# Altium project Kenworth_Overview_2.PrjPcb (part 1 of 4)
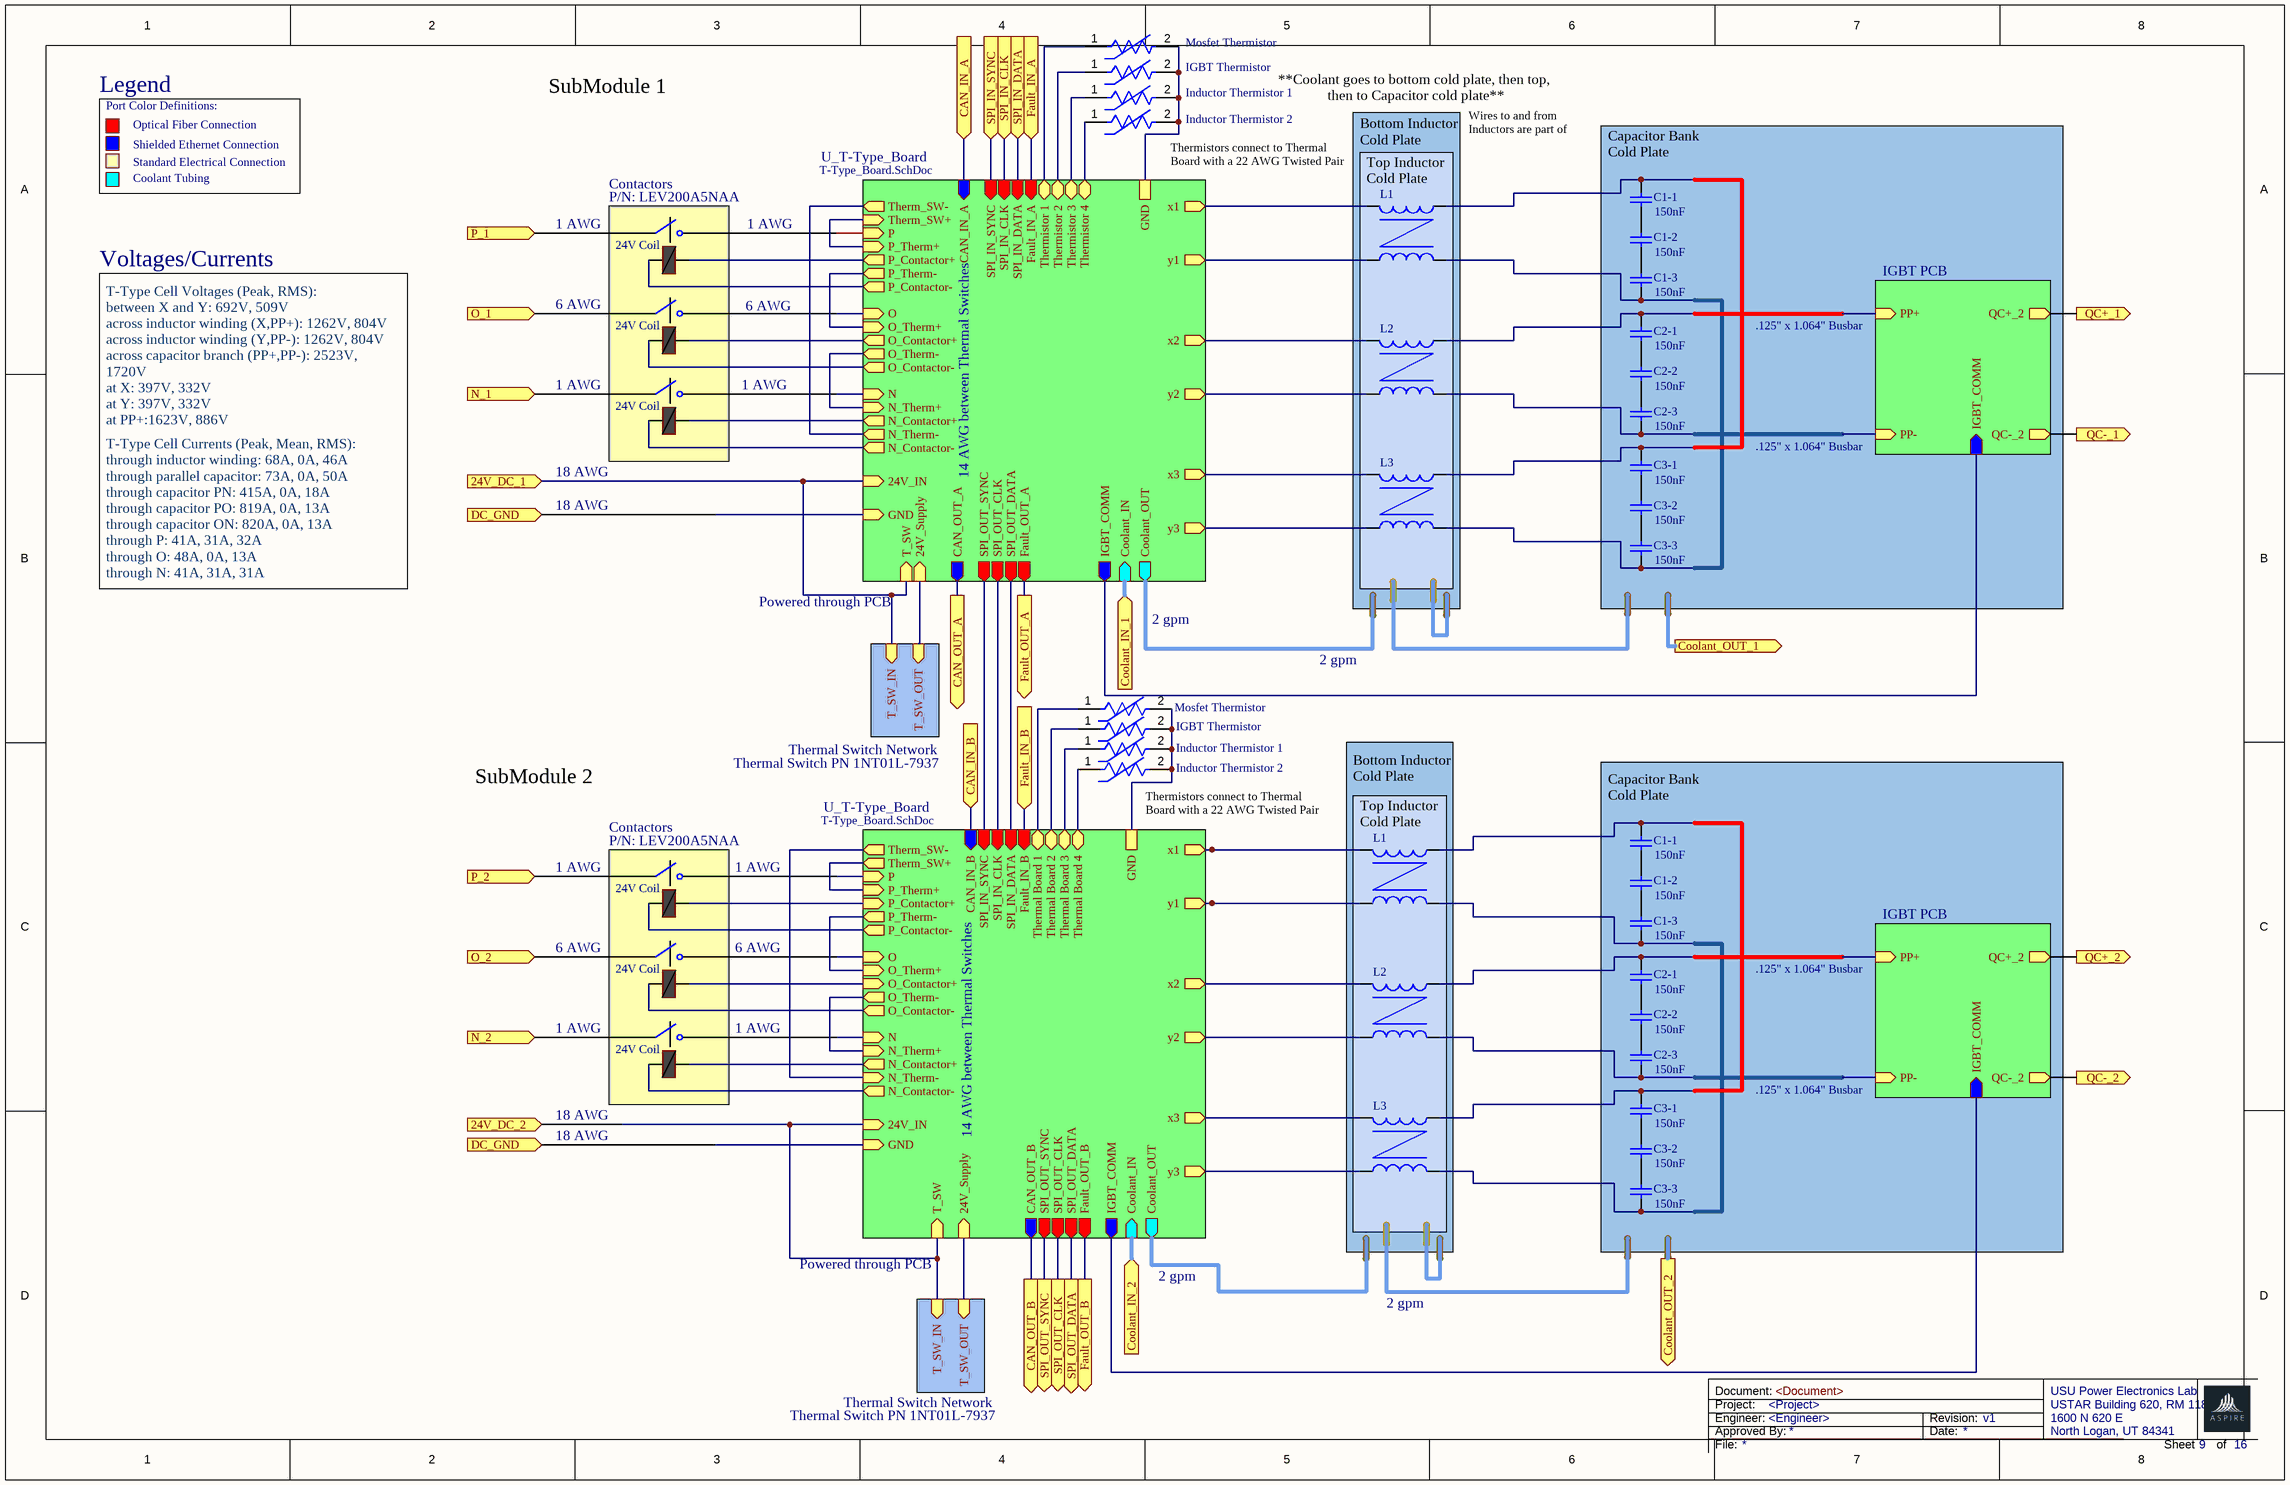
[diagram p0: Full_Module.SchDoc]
19 sheets, 617 parts. Net scope: hierarchical (ports join the sheet entries above them; power ports are global).
Sheets:
  Full_Module.SchDoc
    U_T-Type_Board = T-Type_Board.SchDoc
    U_T-Type_Board = T-Type_Board.SchDoc
    IGBT PCB = T-Type_Board.SchDoc
    IGBT PCB = T-Type_Board.SchDoc
  Primary_Cabinet.SchDoc
    Fuse Block = Fuse_Block.SchDoc
    Unfolder = Unfolder.SchDoc
    T-Type System = T-Type_System.SchDoc
  Coolant_System.SchDoc
  Current_and_Water_Sensing_System.SchDoc
  Top_Overview.SchDoc
    Special Equipment Cabinet = Special_Equipment_Cabinet_Overview.SchDoc
      Shunt Filter = Shunt_Filter.SchDoc
        U_RLC = RLC.SchDoc
        U_RLC = RLC.SchDoc
        U_RLC = RLC.SchDoc
      Auxiliary Circuit = Auxiliary_Circuit.SchDoc
      Relay Circuit = Relay_Circuit.SchDoc
    Secondary Pad = Vehicle_Charger_Hierarchal.SchDoc
      Filter = Filter.SchDoc
      U_Rectifier = Rectifier.SchDoc
    Primary Pad = Underground_Assembly.SchDoc
  Secondary_Pad_Auxiliary_Wiring_Overview.SchDoc

## Sheet Full_Module.SchDoc: <Document>
size Tabloid; Engineer: <Engineer>; Organization: UPEL; Address1: USU Power Electronics Lab; Address2: USTAR Building 620, RM 118; Address3: 1600 N 620 E; Address4: North Logan, UT 84341; DocumentNumber: 9; Revision: v1; SheetNumber: 9; SheetTotal: 16

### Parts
(Parts that share a designator on the sheet are numbered #1, #2 ... from top to bottom, then left to right.)
C1-1#1  value 150nF  [RAD-0.3]  (hidden comment: Cap)
C1-1#2  value 150nF  [RAD-0.3]  (hidden comment: Cap)
C1-2#1  value 150nF  [RAD-0.3]  (hidden comment: Cap)
C1-2#2  value 150nF  [RAD-0.3]  (hidden comment: Cap)
C1-3#1  value 150nF  [RAD-0.3]  (hidden comment: Cap)
C1-3#2  value 150nF  [RAD-0.3]  (hidden comment: Cap)
C2-1#1  value 150nF  [RAD-0.3]  (hidden comment: Cap)
C2-1#2  value 150nF  [RAD-0.3]  (hidden comment: Cap)
C2-2#1  value 150nF  [RAD-0.3]  (hidden comment: Cap)
C2-2#2  value 150nF  [RAD-0.3]  (hidden comment: Cap)
C2-3#1  value 150nF  [RAD-0.3]  (hidden comment: Cap)
C2-3#2  value 150nF  [RAD-0.3]  (hidden comment: Cap)
C3-1#1  value 150nF  [RAD-0.3]  (hidden comment: Cap)
C3-1#2  value 150nF  [RAD-0.3]  (hidden comment: Cap)
C3-2#1  value 150nF  [RAD-0.3]  (hidden comment: Cap)
C3-2#2  value 150nF  [RAD-0.3]  (hidden comment: Cap)
C3-3#1  value 150nF  [RAD-0.3]  (hidden comment: Cap)
C3-3#2  value 150nF  [RAD-0.3]  (hidden comment: Cap)
IGBT_Thermistor#1  NTCALUG01A103J  [FP-NTCALUG01A103J-MFG]  (value not drawn)
IGBT_Thermistor#2  NTCALUG01A103J  [FP-NTCALUG01A103J-MFG]  (value not drawn)
Inductor_Thermistor_1#1  NTCALUG01A103J  [FP-NTCALUG01A103J-MFG]  (value not drawn)
Inductor_Thermistor_1#2  NTCALUG01A103J  [FP-NTCALUG01A103J-MFG]  (value not drawn)
Inductor_Thermistor_2#1  NTCALUG01A103J  [FP-NTCALUG01A103J-MFG]  (value not drawn)
Inductor_Thermistor_2#2  NTCALUG01A103J  [FP-NTCALUG01A103J-MFG]  (value not drawn)
K?#1  Contactor  (value not drawn)
K?#2  Contactor  (value not drawn)
K?#3  Contactor  (value not drawn)
K?#4  Contactor  (value not drawn)
K?#5  Contactor  (value not drawn)
K?#6  Contactor  (value not drawn)
L1#1  Inductor  [0402-A]  (value not drawn)
L1#2  Inductor  [0402-A]  (value not drawn)
L2#1  Inductor  [0402-A]  (value not drawn)
L2#2  Inductor  [0402-A]  (value not drawn)
L3#1  Inductor  [0402-A]  (value not drawn)
L3#2  Inductor  [0402-A]  (value not drawn)
L?#1  Inductor  [0402-A]  (value not drawn)
L?#2  Inductor  [0402-A]  (value not drawn)
L?#3  Inductor  [0402-A]  (value not drawn)
L?#4  Inductor  [0402-A]  (value not drawn)
L?#5  Inductor  [0402-A]  (value not drawn)
L?#6  Inductor  [0402-A]  (value not drawn)
Mosfet_Thermistor#1  NTCALUG01A103J  [FP-NTCALUG01A103J-MFG]  (value not drawn)
Mosfet_Thermistor#2  NTCALUG01A103J  [FP-NTCALUG01A103J-MFG]  (value not drawn)

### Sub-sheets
IGBT PCB = T-Type_Board.SchDoc: QC+_2 (out), QC-_2 (out), PP+ (in), PP- (in), IGBT_COMM (in)
IGBT PCB = T-Type_Board.SchDoc: QC+_2 (out), QC-_2 (out), PP+ (in), PP- (in), IGBT_COMM (in)
Thermal Switch Network = File Name (file not in this document): T_SW_OUT (in), T_SW_IN (in)
Thermal Switch Network = File Name (file not in this document): T_SW_OUT (in), T_SW_IN (in)
U_T-Type_Board = T-Type_Board.SchDoc: P (in), O (in), N (in), CAN_IN_A (in), GND (in), 24V_IN (in), Coolant_IN (in), Coolant_OUT (out), x1 (out), y1 (out), SPI_IN_SYNC (in), CAN_OUT_A (out), SPI_OUT_SYNC (out), Fault_OUT_A (out), SPI_OUT_CLK (out), SPI_OUT_DATA (out), SPI_IN_CLK (in), SPI_IN_DATA (in), Fault_IN_A (in), P_Contactor+ (out), P_Contactor- (out), O_Contactor+ (out), N_Contactor+ (out), O_Contactor- (out), N_Contactor- (out), x2 (out), y2 (out), x3 (out), y3 (out), T_SW (in), 24V_Supply (in), IGBT_COMM (out), P_Therm+ (in), P_Therm- (out), N_Therm- (out), N_Therm+ (in), O_Therm- (out), O_Therm+ (in), Therm_SW+ (in), Therm_SW- (out), Thermistor 4 (bidir), Thermistor 3 (bidir), Thermistor 2 (bidir), Thermistor 1 (bidir), GND
U_T-Type_Board = T-Type_Board.SchDoc: P (in), O (in), N (in), GND (in), 24V_IN (in), Coolant_IN (in), Coolant_OUT (out), SPI_IN_SYNC (in), SPI_OUT_SYNC (out), Fault_OUT_B (out), CAN_OUT_B (out), SPI_OUT_CLK (out), SPI_OUT_DATA (out), CAN_IN_B (in), SPI_IN_CLK (in), SPI_IN_DATA (in), Fault_IN_B (in), P_Contactor+ (in), P_Contactor- (out), O_Contactor+ (in), N_Contactor+ (out), O_Contactor- (out), N_Contactor- (out), x1 (out), y1 (out), x2 (out), y2 (out), x3 (out), y3 (out), T_SW (in), 24V_Supply (in), IGBT_COMM (out), N_Therm+ (in), N_Therm- (in), O_Therm+ (in), O_Therm- (out), P_Therm+ (in), P_Therm- (out), Therm_SW+ (out), Therm_SW- (out), Thermal Board 4 (bidir), Thermal Board 3 (bidir), Thermal Board 2 (bidir), Thermal Board 1 (bidir), GND

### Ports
24V_DC_1 (in), 24V_DC_2 (in), CAN_IN_A (in), CAN_IN_B (in), CAN_OUT_A (out), CAN_OUT_B (out), Coolant_IN_1 (in), Coolant_IN_2 (in), Coolant_OUT_1 (out), Coolant_OUT_2 (out), DC_GND (in), Fault_IN_A (in), Fault_IN_B (in), Fault_OUT_A (out), Fault_OUT_B (out), N_1 (in), N_2 (in), O_1 (in), O_2 (in), P_1 (in), P_2 (in), QC+_1 (out), QC+_2 (out), QC-_1 (out), QC-_2 (out), SPI_IN_CLK (in), SPI_IN_DATA (in), SPI_IN_SYNC (in), SPI_OUT_CLK (out), SPI_OUT_DATA (out), SPI_OUT_SYNC (out)

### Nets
24V_DC_1: port 24V_DC_1, sheet U_T-Type_Board/24V_IN, sheet U_T-Type_Board/T_SW, sheet Thermal Switch Network/T_SW_IN
24V_DC_2: port 24V_DC_2, sheet U_T-Type_Board/24V_IN, sheet U_T-Type_Board/T_SW, sheet Thermal Switch Network/T_SW_IN
CAN_IN_A: port CAN_IN_A, sheet U_T-Type_Board/CAN_IN_A
CAN_IN_B: port CAN_IN_B, sheet U_T-Type_Board/CAN_IN_B
CAN_OUT_A: port CAN_OUT_A, sheet U_T-Type_Board/CAN_OUT_A
CAN_OUT_B: port CAN_OUT_B, sheet U_T-Type_Board/CAN_OUT_B
Coolant_IN_U_T-Type_Board: port Coolant_IN_1, sheet U_T-Type_Board/Coolant_IN
Coolant_IN_U_T-Type_Board: port Coolant_IN_2, sheet U_T-Type_Board/Coolant_IN  [a separate net that carries the same name]
DC_GND: IGBT_Thermistor#1.2 IGBT_Thermistor#2.2 Inductor_Thermistor_1#1.2 Inductor_Thermistor_1#2.2 Inductor_Thermistor_2#1.2 Inductor_Thermistor_2#2.2 Mosfet_Thermistor#1.2 Mosfet_Thermistor#2.2 ; port DC_GND, sheet U_T-Type_Board/GND, sheet U_T-Type_Board/GND, sheet U_T-Type_Board/GND, sheet U_T-Type_Board/GND
Fault_IN_A: port Fault_IN_A, sheet U_T-Type_Board/Fault_IN_A
Fault_IN_B: port Fault_IN_B, sheet U_T-Type_Board/Fault_IN_B
Fault_OUT_A: port Fault_OUT_A, sheet U_T-Type_Board/Fault_OUT_A
Fault_OUT_B: port Fault_OUT_B, sheet U_T-Type_Board/Fault_OUT_B
N: K?#3.4 ; sheet U_T-Type_Board/N
N: K?#6.4 ; sheet U_T-Type_Board/N  [a separate net that carries the same name]
N_1: K?#3.3 ; port N_1
N_2: K?#6.3 ; port N_2
N_Contactor+: K?#3.5 ; sheet U_T-Type_Board/N_Contactor+
N_Contactor+: K?#6.5 ; sheet U_T-Type_Board/N_Contactor+  [a separate net that carries the same name]
N_Contactor-: K?#3.6 ; sheet U_T-Type_Board/N_Contactor-
N_Contactor-: K?#6.6 ; sheet U_T-Type_Board/N_Contactor-  [a separate net that carries the same name]
O: K?#2.4 ; sheet U_T-Type_Board/O
O: K?#5.4 ; sheet U_T-Type_Board/O  [a separate net that carries the same name]
O_1: K?#2.3 ; port O_1
O_2: K?#5.3 ; port O_2
O_Contactor+: K?#2.5 ; sheet U_T-Type_Board/O_Contactor+
O_Contactor+: K?#5.5 ; sheet U_T-Type_Board/O_Contactor+  [a separate net that carries the same name]
O_Contactor-: K?#2.6 ; sheet U_T-Type_Board/O_Contactor-
O_Contactor-: K?#5.6 ; sheet U_T-Type_Board/O_Contactor-  [a separate net that carries the same name]
P: K?#1.4 ; sheet U_T-Type_Board/P
P: K?#4.4 ; sheet U_T-Type_Board/P  [a separate net that carries the same name]
P_1: K?#1.3 ; port P_1
P_2: K?#4.3 ; port P_2
P_Contactor+: K?#1.5 ; sheet U_T-Type_Board/P_Contactor+
P_Contactor+: K?#4.5 ; sheet U_T-Type_Board/P_Contactor+  [a separate net that carries the same name]
P_Contactor-: K?#1.6 ; sheet U_T-Type_Board/P_Contactor-
P_Contactor-: K?#4.6 ; sheet U_T-Type_Board/P_Contactor-  [a separate net that carries the same name]
PP+: C2-1#2.2 L2#2.1 ; sheet IGBT PCB/PP+
PP+: C2-1#1.2 L2#1.1 ; sheet IGBT PCB/PP+  [a separate net that carries the same name]
PP-: C2-3#2.1 L?#5.2 ; sheet IGBT PCB/PP-
PP-: C2-3#1.1 L?#2.2 ; sheet IGBT PCB/PP-  [a separate net that carries the same name]
QC+_1: port QC+_1, sheet IGBT PCB/QC+_2
QC+_2: port QC+_2, sheet IGBT PCB/QC+_2
QC-_1: port QC-_1, sheet IGBT PCB/QC-_2
QC-_2: port QC-_2, sheet IGBT PCB/QC-_2
SPI_IN_CLK: port SPI_IN_CLK, sheet U_T-Type_Board/SPI_IN_CLK
SPI_IN_CLK_U_T-Type_Board: sheet U_T-Type_Board/SPI_OUT_CLK, sheet U_T-Type_Board/SPI_IN_CLK
SPI_IN_DATA: port SPI_IN_DATA, sheet U_T-Type_Board/SPI_IN_DATA
SPI_IN_DATA_U_T-Type_Board: sheet U_T-Type_Board/SPI_OUT_DATA, sheet U_T-Type_Board/SPI_IN_DATA
SPI_IN_SYNC: port SPI_IN_SYNC, sheet U_T-Type_Board/SPI_IN_SYNC
SPI_IN_SYNC_U_T-Type_Board: sheet U_T-Type_Board/SPI_OUT_SYNC, sheet U_T-Type_Board/SPI_IN_SYNC
SPI_OUT_CLK: port SPI_OUT_CLK, sheet U_T-Type_Board/SPI_OUT_CLK
SPI_OUT_DATA: port SPI_OUT_DATA, sheet U_T-Type_Board/SPI_OUT_DATA
SPI_OUT_SYNC: port SPI_OUT_SYNC, sheet U_T-Type_Board/SPI_OUT_SYNC
NetC1-1#1_1: C1-1#1.1 C1-2#1.2
NetC1-1#1_2: C1-1#1.2 C3-1#1.2 L1#1.1 L3#1.1
NetC1-1#2_1: C1-1#2.1 C1-2#2.2
NetC1-1#2_2: C1-1#2.2 C3-1#2.2 L1#2.1 L3#2.1
NetC1-2#1_1: C1-2#1.1 C1-3#1.2
NetC1-2#2_1: C1-2#2.1 C1-3#2.2
NetC1-3#1_1: C1-3#1.1 C3-3#1.1 L?#1.2 L?#3.2
NetC1-3#2_1: C1-3#2.1 C3-3#2.1 L?#4.2 L?#6.2
NetC2-1#1_1: C2-1#1.1 C2-2#1.2
NetC2-1#2_1: C2-1#2.1 C2-2#2.2
NetC2-2#1_1: C2-2#1.1 C2-3#1.2
NetC2-2#2_1: C2-2#2.1 C2-3#2.2
NetC3-1#1_1: C3-1#1.1 C3-2#1.2
NetC3-1#2_1: C3-1#2.1 C3-2#2.2
NetC3-2#1_1: C3-2#1.1 C3-3#1.2
NetC3-2#2_1: C3-2#2.1 C3-3#2.2
NetIGBT_Thermistor#1_1: IGBT_Thermistor#1.1 ; sheet U_T-Type_Board/Thermistor 2
NetIGBT_Thermistor#2_1: IGBT_Thermistor#2.1 ; sheet U_T-Type_Board/Thermal Board 2
NetInductor_Thermistor_1#1_1: Inductor_Thermistor_1#1.1 ; sheet U_T-Type_Board/Thermistor 3
NetInductor_Thermistor_1#2_1: Inductor_Thermistor_1#2.1 ; sheet U_T-Type_Board/Thermal Board 3
NetInductor_Thermistor_2#1_1: Inductor_Thermistor_2#1.1 ; sheet U_T-Type_Board/Thermistor 4
NetInductor_Thermistor_2#2_1: Inductor_Thermistor_2#2.1 ; sheet U_T-Type_Board/Thermal Board 4
NetL1#1_2: L1#1.2 ; sheet U_T-Type_Board/x1
NetL1#2_2: L1#2.2 ; sheet U_T-Type_Board/x1
NetL2#1_2: L2#1.2 ; sheet U_T-Type_Board/x2
NetL2#2_2: L2#2.2 ; sheet U_T-Type_Board/x2
NetL3#1_2: L3#1.2 ; sheet U_T-Type_Board/x3
NetL3#2_2: L3#2.2 ; sheet U_T-Type_Board/x3
NetL?#1_1: L?#1.1 ; sheet U_T-Type_Board/y1
NetL?#2_1: L?#2.1 ; sheet U_T-Type_Board/y2
NetL?#3_1: L?#3.1 ; sheet U_T-Type_Board/y3
NetL?#4_1: L?#4.1 ; sheet U_T-Type_Board/y1
NetL?#5_1: L?#5.1 ; sheet U_T-Type_Board/y2
NetL?#6_1: L?#6.1 ; sheet U_T-Type_Board/y3
NetMosfet_Thermistor#1_1: Mosfet_Thermistor#1.1 ; sheet U_T-Type_Board/Thermistor 1
NetMosfet_Thermistor#2_1: Mosfet_Thermistor#2.1 ; sheet U_T-Type_Board/Thermal Board 1
(unnamed): sheet U_T-Type_Board/24V_Supply, sheet Thermal Switch Network/T_SW_OUT
(unnamed): sheet U_T-Type_Board/IGBT_COMM, sheet IGBT PCB/IGBT_COMM  [a separate net that carries the same name]
(unnamed): sheet U_T-Type_Board/P_Therm+, sheet U_T-Type_Board/Therm_SW+  [a separate net that carries the same name]
(unnamed): sheet U_T-Type_Board/P_Therm-, sheet U_T-Type_Board/O_Therm+  [a separate net that carries the same name]
(unnamed): sheet U_T-Type_Board/N_Therm-, sheet U_T-Type_Board/Therm_SW-  [a separate net that carries the same name]
(unnamed): sheet U_T-Type_Board/N_Therm+, sheet U_T-Type_Board/O_Therm-  [a separate net that carries the same name]
(unnamed): sheet U_T-Type_Board/24V_Supply, sheet Thermal Switch Network/T_SW_OUT  [a separate net that carries the same name]
(unnamed): sheet U_T-Type_Board/IGBT_COMM, sheet IGBT PCB/IGBT_COMM  [a separate net that carries the same name]
(unnamed): sheet U_T-Type_Board/N_Therm+, sheet U_T-Type_Board/O_Therm-  [a separate net that carries the same name]
(unnamed): sheet U_T-Type_Board/N_Therm-, sheet U_T-Type_Board/Therm_SW-  [a separate net that carries the same name]
(unnamed): sheet U_T-Type_Board/O_Therm+, sheet U_T-Type_Board/P_Therm-  [a separate net that carries the same name]
(unnamed): sheet U_T-Type_Board/P_Therm+, sheet U_T-Type_Board/Therm_SW+  [a separate net that carries the same name]

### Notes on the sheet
- Legend
- SubModule 1
- Port Color Definitions:
- Optical Fiber Connection
- Shielded Ethernet Connection
- Standard Electrical Connection
- **Coolant goes to bottom cold plate, then top,
  then to Capacitor cold plate**
- Bottom Inductor Cold Plate
- Wires to and from Inductors are part of custom made inductors
- (near C1-1#1) Capacitor Bank Cold Plate
- Coolant Tubing
- 1 AWG
- (near K?#1) Contactors
- (near K?#1) P/N: LEV200A5NAA
- (near Inductor_Thermistor_2#1) Thermistors connect to Thermal Board with a 22 AWG Twisted Pair with GND
- (near L1#1) Top Inductor Cold Plate
- Voltages/Currents
- (near K?#1) 24V Coil
- 6 AWG
- (near K?#2) 24V Coil
- .125" x 1.064" Busbar
- T-Type Cell Voltages (Peak, RMS):
  between X and Y: 692V, 509V
  across inductor winding (X,PP+): 1262V, 804V
  across inductor winding (Y,PP-): 1262V, 804V
  across capacitor branch (PP+,PP-): 2523V, 1720V
  at X: 397V, 332V
  at Y: 397V, 332V
  at PP+:1623V, 886V
  at PP-: 1623V, 886V
- (near K?#3) 24V Coil
- 18 AWG
- 14 AWG between Thermal Switches
- T-Type Cell Currents (Peak, Mean, RMS):
  through inductor winding: 68A, 0A, 46A
  through parallel capacitor: 73A, 0A, 50A
  through capacitor PN: 415A, 0A, 18A
  through capacitor PO: 819A, 0A, 13A
  through capacitor ON: 820A, 0A, 13A
  through P: 41A, 31A, 32A
  through O: 48A, 0A, 13A
  through N: 41A, 31A, 31A
- Powered through PCB
- 2 gpm
- Thermal Switch PN 1NT01L-7937
- Thermal Switch Network
- SubModule 2
- (near K?#4) Contactors
- (near Inductor_Thermistor_2#2) Thermistors connect to Thermal Board with a 22 AWG Twisted Pair with GND
- (near L1#2) Top Inductor Cold Plate
- (near C1-1#2) Capacitor Bank Cold Plate
- (near K?#4) P/N: LEV200A5NAA
- (near K?#4) 24V Coil
- (near K?#4) 1 AWG
- (near K?#5) 24V Coil
- (near K?#5) 6 AWG
- (near K?#6) 1 AWG
- (near K?#6) 24V Coil

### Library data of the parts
C1-1#1 C1-1#2 C1-2#1 C1-2#2 C1-3#1 C1-3#2 C2-1#1 C2-1#2 C2-2#1 C2-2#2 C2-3#1 C2-3#2 C3-1#1 C3-1#2 C3-2#1 C3-2#2 C3-3#1 C3-3#2 = Cap: Capacitor
IGBT_Thermistor#1 IGBT_Thermistor#2 Inductor_Thermistor_1#1 Inductor_Thermistor_1#2 Inductor_Thermistor_2#1 Inductor_Thermistor_2#2 Mosfet_Thermistor#1 Mosfet_Thermistor#2 = CMP-009-00000-2: NTC Thermistor, 10000ohm, Chassis Mount
L1#1 L1#2 L2#1 L2#2 L3#1 L3#2 L?#1-L?#6 = Inductor: Code_IEC: 1005; Value: 10mH

## Sheet T-Type_Board.SchDoc: <Document>
size Letter; Engineer: <Engineer>; Organization: UPEL; Address1: USU Power Electronics Lab; Address2: USTAR Building 620, RM 118; Address3: 1600 N 620 E; Address4: North Logan, UT 84341; DocumentNumber: 10; Revision: v1; SheetNumber: 10; SheetTotal: 16
Used 4 times, as channels U_T-Type_Board, U_T-Type_Board, IGBT PCB, IGBT PCB. Parts and nets are listed once, with the designators drawn on the sheet.
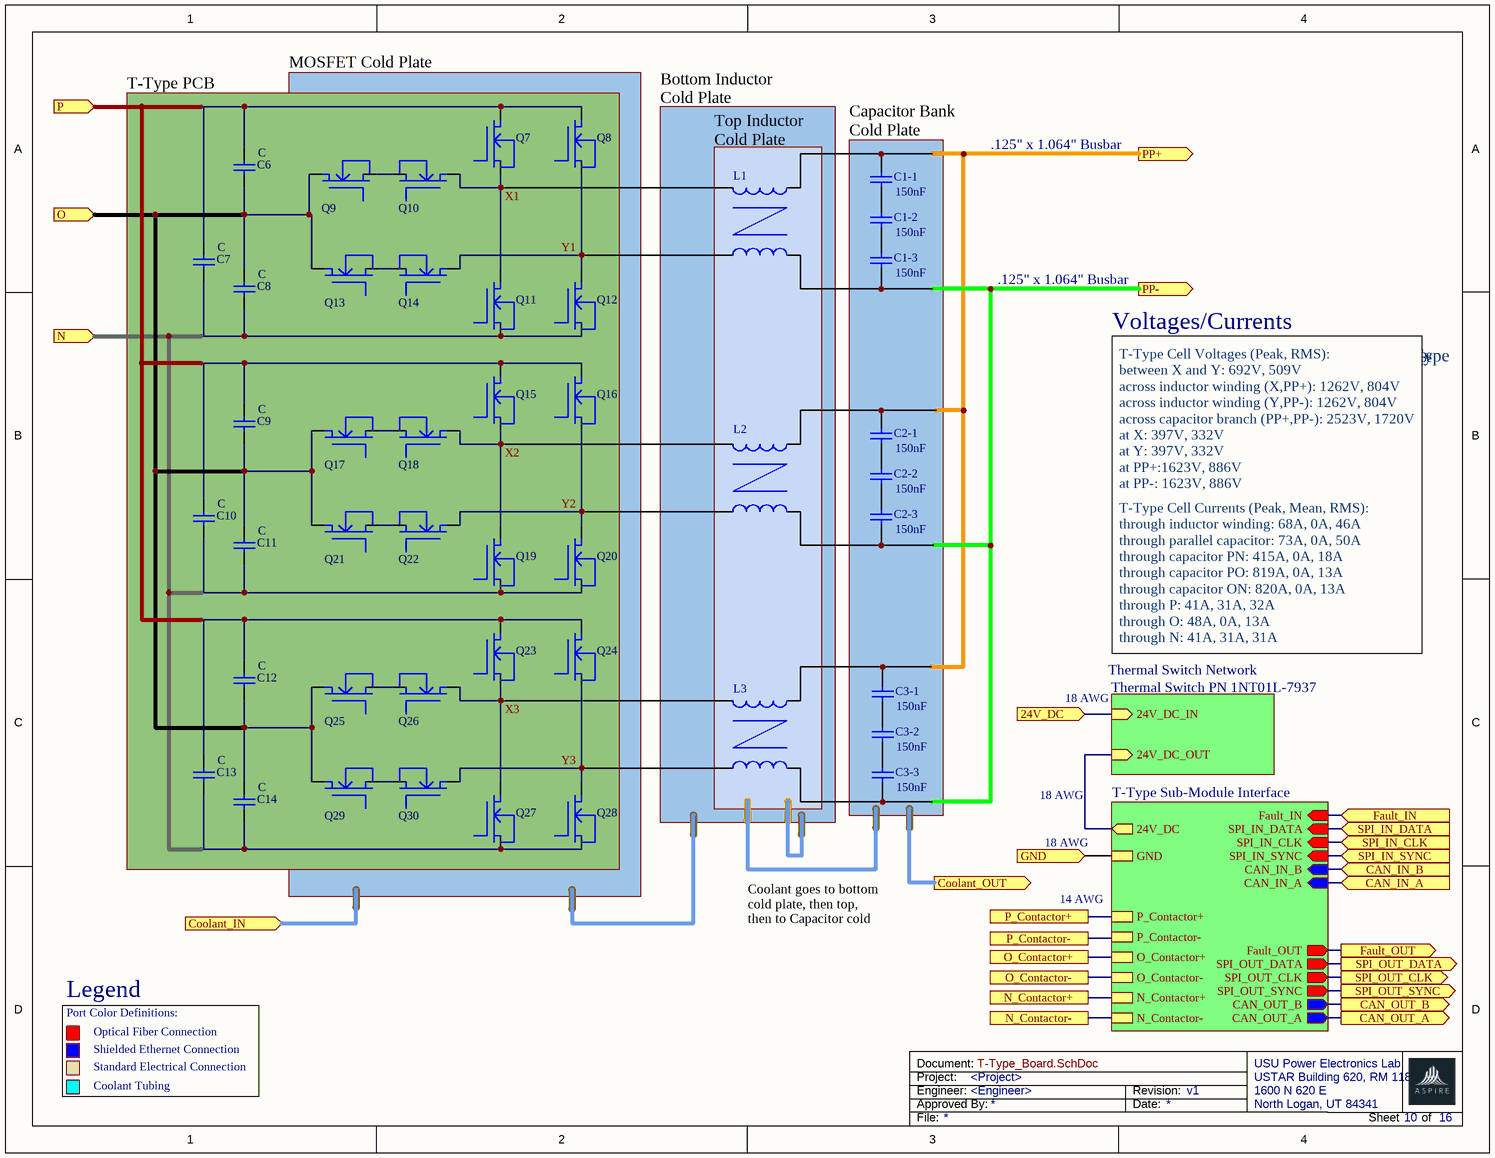
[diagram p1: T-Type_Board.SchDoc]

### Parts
(Parts that share a designator on the sheet are numbered #1, #2 ... from top to bottom, then left to right.)
C1-1  value 150nF  [RAD-0.3]  (hidden comment: Cap)
C1-2  value 150nF  [RAD-0.3]  (hidden comment: Cap)
C1-3  value 150nF  [RAD-0.3]  (hidden comment: Cap)
C2-1  value 150nF  [RAD-0.3]  (hidden comment: Cap)
C2-2  value 150nF  [RAD-0.3]  (hidden comment: Cap)
C2-3  value 150nF  [RAD-0.3]  (hidden comment: Cap)
C3-1  value 150nF  [RAD-0.3]  (hidden comment: Cap)
C3-2  value 150nF  [RAD-0.3]  (hidden comment: Cap)
C3-3  value 150nF  [RAD-0.3]  (hidden comment: Cap)
C6  C  [RAD-0.3]
C7  C  [RAD-0.3]
C8  C  [RAD-0.3]
C9  C  [RAD-0.3]
C10  C  [RAD-0.3]
C11  C  [RAD-0.3]
C12  C  [RAD-0.3]
C13  C  [RAD-0.3]
C14  C  [RAD-0.3]
L1  Inductor  [0402-A]  (value not drawn)
L2  Inductor  [0402-A]  (value not drawn)
L3  Inductor  [0402-A]  (value not drawn)
L?#1  Inductor  [0402-A]  (value not drawn)
L?#2  Inductor  [0402-A]  (value not drawn)
L?#3  Inductor  [0402-A]  (value not drawn)
Q7  T-Cell_component  (value not drawn)
Q8  T-Cell_component  (value not drawn)
Q9  T-Cell_component  (value not drawn)
Q10  T-Cell_component  (value not drawn)
Q11  T-Cell_component  (value not drawn)
Q12  T-Cell_component  (value not drawn)
Q13  T-Cell_component  (value not drawn)
Q14  T-Cell_component  (value not drawn)
Q15  T-Cell_component  (value not drawn)
Q16  T-Cell_component  (value not drawn)
Q17  T-Cell_component  (value not drawn)
Q18  T-Cell_component  (value not drawn)
Q19  T-Cell_component  (value not drawn)
Q20  T-Cell_component  (value not drawn)
Q21  T-Cell_component  (value not drawn)
Q22  T-Cell_component  (value not drawn)
Q23  T-Cell_component  (value not drawn)
Q24  T-Cell_component  (value not drawn)
Q25  T-Cell_component  (value not drawn)
Q26  T-Cell_component  (value not drawn)
Q27  T-Cell_component  (value not drawn)
Q28  T-Cell_component  (value not drawn)
Q29  T-Cell_component  (value not drawn)
Q30  T-Cell_component  (value not drawn)

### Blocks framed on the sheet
MOSFET Cold Plate: Q7-Q30

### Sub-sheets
T-Type Sub-Module Interface = File Name (file not in this document): 24V_DC (out), GND, CAN_IN_A (in), SPI_IN_SYNC (in), CAN_IN_B (in), SPI_IN_CLK (in), SPI_IN_DATA (in), Fault_IN (in), CAN_OUT_A (out), SPI_OUT_SYNC (out), Fault_OUT (out), CAN_OUT_B (out), SPI_OUT_CLK (out), SPI_OUT_DATA (out), P_Contactor+, P_Contactor-, O_Contactor+, O_Contactor-, N_Contactor+, N_Contactor-
Thermal Switch Network = File Name (file not in this document): 24V_DC_IN (in), 24V_DC_OUT (in)

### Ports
24V_DC (in), CAN_IN_A (in), CAN_IN_B (in), CAN_OUT_A (out), CAN_OUT_B (out), Coolant_IN (in), Coolant_OUT (out), Fault_IN (in), Fault_OUT (out), GND (in), N (in), N_Contactor+, N_Contactor-, O (in), O_Contactor+, O_Contactor-, P (in), P_Contactor+, P_Contactor-, PP+ (out), PP- (out), SPI_IN_CLK (in), SPI_IN_DATA (in), SPI_IN_SYNC (in), SPI_OUT_CLK (out), SPI_OUT_DATA (out), SPI_OUT_SYNC (out)

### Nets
24V_DC: port 24V_DC, sheet Thermal Switch Network/24V_DC_IN
CAN_IN_A: port CAN_IN_A, sheet T-Type Sub-Module Interface/CAN_IN_A
CAN_IN_B: port CAN_IN_B, sheet T-Type Sub-Module Interface/CAN_IN_B
CAN_OUT_A: port CAN_OUT_A, sheet T-Type Sub-Module Interface/CAN_OUT_A
CAN_OUT_B: port CAN_OUT_B, sheet T-Type Sub-Module Interface/CAN_OUT_B
Fault_IN: port Fault_IN, sheet T-Type Sub-Module Interface/Fault_IN
Fault_OUT: port Fault_OUT, sheet T-Type Sub-Module Interface/Fault_OUT
GND: port GND, sheet T-Type Sub-Module Interface/GND
N_Contactor+: port N_Contactor+, sheet T-Type Sub-Module Interface/N_Contactor+
N_Contactor-: port N_Contactor-, sheet T-Type Sub-Module Interface/N_Contactor-
O: C9.1 C11.2 Q17.4 Q21.4 ; port O
O_Contactor+: port O_Contactor+, sheet T-Type Sub-Module Interface/O_Contactor+
O_Contactor-: port O_Contactor-, sheet T-Type Sub-Module Interface/O_Contactor-
P_Contactor+: port P_Contactor+, sheet T-Type Sub-Module Interface/P_Contactor+
PP+: C1-1.2 C2-1.2 C3-1.2 L1.1 L2.1 L3.1 ; port PP+
PP-: C1-3.1 C2-3.1 C3-3.1 L?#1.2 L?#2.2 L?#3.2 ; port PP-
SPI_IN_CLK: port SPI_IN_CLK, sheet T-Type Sub-Module Interface/SPI_IN_CLK
SPI_IN_DATA: port SPI_IN_DATA, sheet T-Type Sub-Module Interface/SPI_IN_DATA
SPI_IN_SYNC: port SPI_IN_SYNC, sheet T-Type Sub-Module Interface/SPI_IN_SYNC
SPI_OUT_CLK: port SPI_OUT_CLK, sheet T-Type Sub-Module Interface/SPI_OUT_CLK
SPI_OUT_DATA: port SPI_OUT_DATA, sheet T-Type Sub-Module Interface/SPI_OUT_DATA
SPI_OUT_SYNC: port SPI_OUT_SYNC, sheet T-Type Sub-Module Interface/SPI_OUT_SYNC
X1: L1.2 Q7.5 Q10.4 Q11.4
X2: L2.2 Q15.5 Q18.4 Q19.4
X3: L3.2 Q23.5 Q26.4 Q27.4
Y1: L?#1.1 Q8.5 Q12.4 Q14.4
Y2: L?#2.1 Q16.5 Q20.4 Q22.4
Y3: L?#3.1 Q24.5 Q28.4 Q30.4
NetC1-1_1: C1-1.1 C1-2.2
NetC1-2_1: C1-2.1 C1-3.2
NetC2-1_1: C2-1.1 C2-2.2
NetC2-2_1: C2-2.1 C2-3.2
NetC3-1_1: C3-1.1 C3-2.2
NetC3-2_1: C3-2.1 C3-3.2
NetC6_1: C6.1 C8.2 Q9.4 Q13.4
NetC6_2: C6.2 C7.2 Q7.4 Q8.4
NetC7_1: C7.1 C8.1 Q11.5 Q12.5
NetC9_2: C9.2 C10.2 Q15.4 Q16.4
NetC10_1: C10.1 C11.1 Q19.5 Q20.5
NetC12_1: C12.1 C14.2 Q25.4 Q29.4
NetC12_2: C12.2 C13.2 Q23.4 Q24.4
NetC13_1: C13.1 C14.1 Q27.5 Q28.5
NetQ9_5: Q9.5 Q10.5
NetQ13_5: Q13.5 Q14.5
NetQ17_5: Q17.5 Q18.5
NetQ21_5: Q21.5 Q22.5
NetQ25_5: Q25.5 Q26.5
NetQ29_5: Q29.5 Q30.5
(unnamed): sheet T-Type Sub-Module Interface/24V_DC, sheet Thermal Switch Network/24V_DC_OUT

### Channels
U_T-Type_Board: designators C1-1=C1-1_U_T-Type_Board#1 C1-2=C1-2_U_T-Type_Board#1 C1-3=C1-3_U_T-Type_Board#1 C2-1=C2-1_U_T-Type_Board#1 C2-2=C2-2_U_T-Type_Board#1 C2-3=C2-3_U_T-Type_Board#1 C3-1=C3-1_U_T-Type_Board#1 C3-2=C3-2_U_T-Type_Board#1 C3-3=C3-3_U_T-Type_Board#1 C6=C6_U_T-Type_Board#1 C7=C7_U_T-Type_Board#1 C8=C8_U_T-Type_Board#1 C9=C9_U_T-Type_Board#1 C10=C10_U_T-Type_Board#1 C11=C11_U_T-Type_Board#1 C12=C12_U_T-Type_Board#1 C13=C13_U_T-Type_Board#1 C14=C14_U_T-Type_Board#1 L1=L1_U_T-Type_Board#1 L2=L2_U_T-Type_Board#1 L3=L3_U_T-Type_Board#1 L?=L?_U_T-Type_Board#1 L?=L?_U_T-Type_Board#2 L?=L?_U_T-Type_Board#3 Q7=Q7_U_T-Type_Board#1 Q8=Q8_U_T-Type_Board#1 Q9=Q9_U_T-Type_Board#1 Q10=Q10_U_T-Type_Board#1 Q11=Q11_U_T-Type_Board#1 Q12=Q12_U_T-Type_Board#1 Q13=Q13_U_T-Type_Board#1 Q14=Q14_U_T-Type_Board#1 Q15=Q15_U_T-Type_Board#1 Q16=Q16_U_T-Type_Board#1 Q17=Q17_U_T-Type_Board#1 Q18=Q18_U_T-Type_Board#1 Q19=Q19_U_T-Type_Board#1 Q20=Q20_U_T-Type_Board#1 Q21=Q21_U_T-Type_Board#1 Q22=Q22_U_T-Type_Board#1 Q23=Q23_U_T-Type_Board#1 Q24=Q24_U_T-Type_Board#1 Q25=Q25_U_T-Type_Board#1 Q26=Q26_U_T-Type_Board#1 Q27=Q27_U_T-Type_Board#1 Q28=Q28_U_T-Type_Board#1 Q29=Q29_U_T-Type_Board#1 Q30=Q30_U_T-Type_Board#1; ports 24V_DC=24V_DC_U_T-Type_Board CAN_IN_A=CAN_IN_A CAN_IN_B=CAN_IN_B_U_T-Type_Board CAN_OUT_A=CAN_OUT_A CAN_OUT_B=CAN_OUT_B_U_T-Type_Board Coolant_IN=Coolant_IN_U_T-Type_Board Coolant_OUT=Coolant_OUT_U_T-Type_Board Fault_IN=Fault_IN_U_T-Type_Board Fault_OUT=Fault_OUT_U_T-Type_Board GND=DC_GND N=N N_Contactor+=N_Contactor+ N_Contactor-=N_Contactor- O=O O_Contactor+=O_Contactor+ O_Contactor-=O_Contactor- P=P P_Contactor+=P_Contactor+ P_Contactor-=P_Contactor- PP+=PP+_U_T-Type_Board PP-=PP-_U_T-Type_Board SPI_IN_CLK=SPI_IN_CLK SPI_IN_DATA=SPI_IN_DATA SPI_IN_SYNC=SPI_IN_SYNC SPI_OUT_CLK=SPI_IN_CLK_U_T-Type_Board SPI_OUT_DATA=SPI_IN_DATA_U_T-Type_Board SPI_OUT_SYNC=SPI_IN_SYNC_U_T-Type_Board
U_T-Type_Board: designators C1-1=C1-1_U_T-Type_Board#2 C1-2=C1-2_U_T-Type_Board#2 C1-3=C1-3_U_T-Type_Board#2 C2-1=C2-1_U_T-Type_Board#2 C2-2=C2-2_U_T-Type_Board#2 C2-3=C2-3_U_T-Type_Board#2 C3-1=C3-1_U_T-Type_Board#2 C3-2=C3-2_U_T-Type_Board#2 C3-3=C3-3_U_T-Type_Board#2 C6=C6_U_T-Type_Board#2 C7=C7_U_T-Type_Board#2 C8=C8_U_T-Type_Board#2 C9=C9_U_T-Type_Board#2 C10=C10_U_T-Type_Board#2 C11=C11_U_T-Type_Board#2 C12=C12_U_T-Type_Board#2 C13=C13_U_T-Type_Board#2 C14=C14_U_T-Type_Board#2 L1=L1_U_T-Type_Board#2 L2=L2_U_T-Type_Board#2 L3=L3_U_T-Type_Board#2 L?=L?_U_T-Type_Board#4 L?=L?_U_T-Type_Board#5 L?=L?_U_T-Type_Board#6 Q7=Q7_U_T-Type_Board#2 Q8=Q8_U_T-Type_Board#2 Q9=Q9_U_T-Type_Board#2 Q10=Q10_U_T-Type_Board#2 Q11=Q11_U_T-Type_Board#2 Q12=Q12_U_T-Type_Board#2 Q13=Q13_U_T-Type_Board#2 Q14=Q14_U_T-Type_Board#2 Q15=Q15_U_T-Type_Board#2 Q16=Q16_U_T-Type_Board#2 Q17=Q17_U_T-Type_Board#2 Q18=Q18_U_T-Type_Board#2 Q19=Q19_U_T-Type_Board#2 Q20=Q20_U_T-Type_Board#2 Q21=Q21_U_T-Type_Board#2 Q22=Q22_U_T-Type_Board#2 Q23=Q23_U_T-Type_Board#2 Q24=Q24_U_T-Type_Board#2 Q25=Q25_U_T-Type_Board#2 Q26=Q26_U_T-Type_Board#2 Q27=Q27_U_T-Type_Board#2 Q28=Q28_U_T-Type_Board#2 Q29=Q29_U_T-Type_Board#2 Q30=Q30_U_T-Type_Board#2; ports 24V_DC=24V_DC_U_T-Type_Board CAN_IN_A=CAN_IN_A_U_T-Type_Board CAN_IN_B=CAN_IN_B CAN_OUT_A=CAN_OUT_A_U_T-Type_Board CAN_OUT_B=CAN_OUT_B Coolant_IN=Coolant_IN_U_T-Type_Board Coolant_OUT=Coolant_OUT_U_T-Type_Board Fault_IN=Fault_IN_U_T-Type_Board Fault_OUT=Fault_OUT_U_T-Type_Board GND=DC_GND N=N N_Contactor+=N_Contactor+ N_Contactor-=N_Contactor- O=O O_Contactor+=O_Contactor+ O_Contactor-=O_Contactor- P=P P_Contactor+=P_Contactor+ P_Contactor-=P_Contactor- PP+=PP+_U_T-Type_Board PP-=PP-_U_T-Type_Board SPI_IN_CLK=SPI_IN_CLK_U_T-Type_Board SPI_IN_DATA=SPI_IN_DATA_U_T-Type_Board SPI_IN_SYNC=SPI_IN_SYNC_U_T-Type_Board SPI_OUT_CLK=SPI_OUT_CLK SPI_OUT_DATA=SPI_OUT_DATA SPI_OUT_SYNC=SPI_OUT_SYNC
IGBT PCB: designators C1-1=C1-1_IGBT_PCB#1 C1-2=C1-2_IGBT_PCB#1 C1-3=C1-3_IGBT_PCB#1 C2-1=C2-1_IGBT_PCB#1 C2-2=C2-2_IGBT_PCB#1 C2-3=C2-3_IGBT_PCB#1 C3-1=C3-1_IGBT_PCB#1 C3-2=C3-2_IGBT_PCB#1 C3-3=C3-3_IGBT_PCB#1 C6=C6_IGBT_PCB#1 C7=C7_IGBT_PCB#1 C8=C8_IGBT_PCB#1 C9=C9_IGBT_PCB#1 C10=C10_IGBT_PCB#1 C11=C11_IGBT_PCB#1 C12=C12_IGBT_PCB#1 C13=C13_IGBT_PCB#1 C14=C14_IGBT_PCB#1 L1=L1_IGBT_PCB#1 L2=L2_IGBT_PCB#1 L3=L3_IGBT_PCB#1 L?=L?_IGBT_PCB#1 L?=L?_IGBT_PCB#2 L?=L?_IGBT_PCB#3 Q7=Q7_IGBT_PCB#1 Q8=Q8_IGBT_PCB#1 Q9=Q9_IGBT_PCB#1 Q10=Q10_IGBT_PCB#1 Q11=Q11_IGBT_PCB#1 Q12=Q12_IGBT_PCB#1 Q13=Q13_IGBT_PCB#1 Q14=Q14_IGBT_PCB#1 Q15=Q15_IGBT_PCB#1 Q16=Q16_IGBT_PCB#1 Q17=Q17_IGBT_PCB#1 Q18=Q18_IGBT_PCB#1 Q19=Q19_IGBT_PCB#1 Q20=Q20_IGBT_PCB#1 Q21=Q21_IGBT_PCB#1 Q22=Q22_IGBT_PCB#1 Q23=Q23_IGBT_PCB#1 Q24=Q24_IGBT_PCB#1 Q25=Q25_IGBT_PCB#1 Q26=Q26_IGBT_PCB#1 Q27=Q27_IGBT_PCB#1 Q28=Q28_IGBT_PCB#1 Q29=Q29_IGBT_PCB#1 Q30=Q30_IGBT_PCB#1; ports 24V_DC=24V_DC_IGBT PCB CAN_IN_A=CAN_IN_A_IGBT PCB CAN_IN_B=CAN_IN_B_IGBT PCB CAN_OUT_A=CAN_OUT_A_IGBT PCB CAN_OUT_B=CAN_OUT_B_IGBT PCB Coolant_IN=Coolant_IN_IGBT PCB Coolant_OUT=Coolant_OUT_IGBT PCB Fault_IN=Fault_IN_IGBT PCB Fault_OUT=Fault_OUT_IGBT PCB GND=GND_IGBT PCB N=N_IGBT PCB N_Contactor+=N_Contactor+_IGBT PCB N_Contactor-=N_Contactor-_IGBT PCB O=O_IGBT PCB O_Contactor+=O_Contactor+_IGBT PCB O_Contactor-=O_Contactor-_IGBT PCB P=P_IGBT PCB P_Contactor+=P_Contactor+_IGBT PCB P_Contactor-=P_Contactor-_IGBT PCB PP+=PP+ PP-=PP- SPI_IN_CLK=SPI_IN_CLK_IGBT PCB SPI_IN_DATA=SPI_IN_DATA_IGBT PCB SPI_IN_SYNC=SPI_IN_SYNC_IGBT PCB SPI_OUT_CLK=SPI_OUT_CLK_IGBT PCB SPI_OUT_DATA=SPI_OUT_DATA_IGBT PCB SPI_OUT_SYNC=SPI_OUT_SYNC_IGBT PCB
IGBT PCB: designators C1-1=C1-1_IGBT_PCB#2 C1-2=C1-2_IGBT_PCB#2 C1-3=C1-3_IGBT_PCB#2 C2-1=C2-1_IGBT_PCB#2 C2-2=C2-2_IGBT_PCB#2 C2-3=C2-3_IGBT_PCB#2 C3-1=C3-1_IGBT_PCB#2 C3-2=C3-2_IGBT_PCB#2 C3-3=C3-3_IGBT_PCB#2 C6=C6_IGBT_PCB#2 C7=C7_IGBT_PCB#2 C8=C8_IGBT_PCB#2 C9=C9_IGBT_PCB#2 C10=C10_IGBT_PCB#2 C11=C11_IGBT_PCB#2 C12=C12_IGBT_PCB#2 C13=C13_IGBT_PCB#2 C14=C14_IGBT_PCB#2 L1=L1_IGBT_PCB#2 L2=L2_IGBT_PCB#2 L3=L3_IGBT_PCB#2 L?=L?_IGBT_PCB#4 L?=L?_IGBT_PCB#5 L?=L?_IGBT_PCB#6 Q7=Q7_IGBT_PCB#2 Q8=Q8_IGBT_PCB#2 Q9=Q9_IGBT_PCB#2 Q10=Q10_IGBT_PCB#2 Q11=Q11_IGBT_PCB#2 Q12=Q12_IGBT_PCB#2 Q13=Q13_IGBT_PCB#2 Q14=Q14_IGBT_PCB#2 Q15=Q15_IGBT_PCB#2 Q16=Q16_IGBT_PCB#2 Q17=Q17_IGBT_PCB#2 Q18=Q18_IGBT_PCB#2 Q19=Q19_IGBT_PCB#2 Q20=Q20_IGBT_PCB#2 Q21=Q21_IGBT_PCB#2 Q22=Q22_IGBT_PCB#2 Q23=Q23_IGBT_PCB#2 Q24=Q24_IGBT_PCB#2 Q25=Q25_IGBT_PCB#2 Q26=Q26_IGBT_PCB#2 Q27=Q27_IGBT_PCB#2 Q28=Q28_IGBT_PCB#2 Q29=Q29_IGBT_PCB#2 Q30=Q30_IGBT_PCB#2; ports 24V_DC=24V_DC_IGBT PCB CAN_IN_A=CAN_IN_A_IGBT PCB CAN_IN_B=CAN_IN_B_IGBT PCB CAN_OUT_A=CAN_OUT_A_IGBT PCB CAN_OUT_B=CAN_OUT_B_IGBT PCB Coolant_IN=Coolant_IN_IGBT PCB Coolant_OUT=Coolant_OUT_IGBT PCB Fault_IN=Fault_IN_IGBT PCB Fault_OUT=Fault_OUT_IGBT PCB GND=GND_IGBT PCB N=N_IGBT PCB N_Contactor+=N_Contactor+_IGBT PCB N_Contactor-=N_Contactor-_IGBT PCB O=O_IGBT PCB O_Contactor+=O_Contactor+_IGBT PCB O_Contactor-=O_Contactor-_IGBT PCB P=P_IGBT PCB P_Contactor+=P_Contactor+_IGBT PCB P_Contactor-=P_Contactor-_IGBT PCB PP+=PP+ PP-=PP- SPI_IN_CLK=SPI_IN_CLK_IGBT PCB SPI_IN_DATA=SPI_IN_DATA_IGBT PCB SPI_IN_SYNC=SPI_IN_SYNC_IGBT PCB SPI_OUT_CLK=SPI_OUT_CLK_IGBT PCB SPI_OUT_DATA=SPI_OUT_DATA_IGBT PCB SPI_OUT_SYNC=SPI_OUT_SYNC_IGBT PCB

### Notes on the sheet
- T-Type PCB
- Bottom Inductor Cold Plate
- Top Inductor Cold Plate
- (near C1-1) Capacitor Bank Cold Plate
- .125" x 1.064" Busbar
- Voltages/Currents
- T-Type Cell RMS Voltages:
  between X and Y: 510V
  across inductor winding (X,PP+): 803V
  across inductor winding (Y,PP-): 803V
  across capacitor branch (PP+,PP-): 1720V
  at X: 330V
  at Y: 330V
  at PP+: 890V
  at PP-: 890V
- T-Type Cell RMS Currents:
  through inductor winding: 47A
  through parallel capacitor: 50A
  through P: 32A
  through N: 31A
  through capacitor PN: 17.7A
  through capacitor PO: 13A
  through capacitor ON: 13A
- T-Type Cell Mean Currents:
  through P: 31A
  through N: 31A
- T-Type Cell Max Voltages:
  between X and Y: 692V
  across inductor winding (X,PP+): 1261V
  across inductor winding (Y,PP-): 1261V
  across capacitor branch (PP+,PP-): 2523V
  at X: 397V
  at Y: 397V
  at PP+:1620V
  at PP-: 1620V
- T-Type Cell MAX Currents:
  through inductor winding: 69A
  through parallel capacitor: 73A
  through P: 41A
  through N: 41A
- T-Type Cell Voltages (Peak, RMS):
  between X and Y: 692V, 509V
  across inductor winding (X,PP+): 1262V, 804V
  across inductor winding (Y,PP-): 1262V, 804V
  across capacitor branch (PP+,PP-): 2523V, 1720V
  at X: 397V, 332V
  at Y: 397V, 332V
  at PP+:1623V, 886V
  at PP-: 1623V, 886V
- T-Type Cell Currents (Peak, Mean, RMS):
  through inductor winding: 68A, 0A, 46A
  through parallel capacitor: 73A, 0A, 50A
  through capacitor PN: 415A, 0A, 18A
  through capacitor PO: 819A, 0A, 13A
  through capacitor ON: 820A, 0A, 13A
  through P: 41A, 31A, 32A
  through O: 48A, 0A, 13A
  through N: 41A, 31A, 31A
- 18 AWG
- Thermal Switch PN 1NT01L-7937
- 14 AWG
- Coolant goes to bottom cold plate, then top, then to Capacitor cold plate
- Legend
- Port Color Definitions:
- Optical Fiber Connection
- Shielded Ethernet Connection
- Standard Electrical Connection
- Coolant Tubing

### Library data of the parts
C1-1-C1-3 C2-1-C2-3 C3-1-C3-3 = Cap: Capacitor
C6-C14 = Cap: Capacitor; Value: 100pF
L1-L3 L?#1-L?#3 = Inductor: Code_IEC: 1005; Value: 10mH

## Sheet Primary_Cabinet.SchDoc: <Document>
size Letter; Engineer: <Engineer>; Organization: UPEL; Address1: USU Power Electronics Lab; Address2: USTAR Building 620, RM 118; Address3: 1600 N 620 E; Address4: North Logan, UT 84341; DocumentNumber: 5; Revision: v1; SheetNumber: 5; SheetTotal: 16
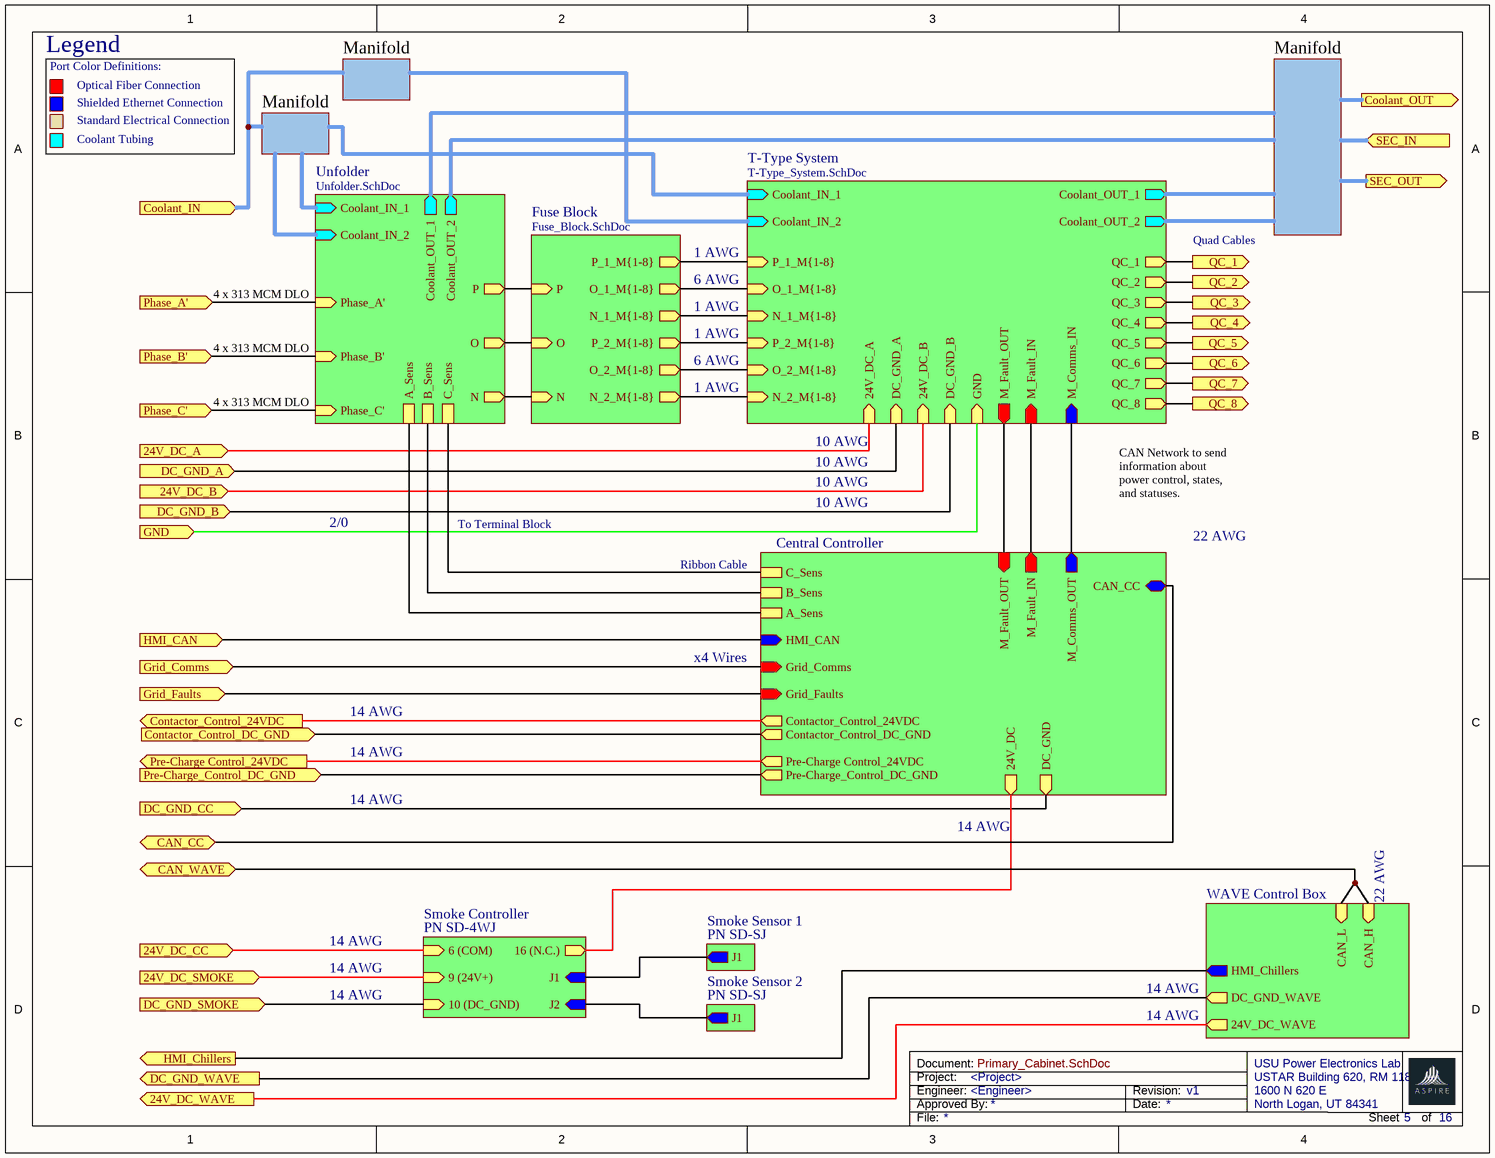
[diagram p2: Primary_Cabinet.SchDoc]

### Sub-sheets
Central Controller = File Name (file not in this document): HMI_CAN (in), Grid_Comms (in), Grid_Faults (in), 24V_DC (out), Contactor_Control_24VDC (out), Contactor_Control_DC_GND (out), M_Fault_OUT (in), M_Fault_IN (out), M_Comms_OUT (out), DC_GND (out), Pre-Charge_Control_DC_GND (out), Pre-Charge Control_24VDC (out), CAN_CC (bidir), C_Sens, B_Sens, A_Sens
Fuse Block = Fuse_Block.SchDoc: P (in), O (in), N (in), N_2_M{1-8} (out), O_2_M{1-8} (out), P_2_M{1-8} (out), N_1_M{1-8} (out), O_1_M{1-8} (out), P_1_M{1-8} (out)
Smoke Controller = PN SD-4WJ (file not in this document): 10 (DC_GND) (in), 9 (24V+) (in), 16 (N.C.) (out), 6 (COM) (in), J1 (in), J2 (in)
Smoke Sensor 1 = PN SD-SJ (file not in this document): J1 (out)
Smoke Sensor 2 = PN SD-SJ (file not in this document): J1 (out)
T-Type System = T-Type_System.SchDoc: Coolant_IN_1 (in), Coolant_OUT_1 (out), QC_2 (out), QC_1 (out), QC_3 (out), QC_6 (out), QC_7 (out), QC_8 (out), QC_5 (out), QC_4 (out), N_2_M{1-8} (in), O_2_M{1-8} (in), P_2_M{1-8} (in), N_1_M{1-8} (in), O_1_M{1-8} (in), P_1_M{1-8} (in), M_Fault_OUT (out), M_Comms_IN (in), M_Fault_IN (in), 24V_DC_B (in), 24V_DC_A (in), DC_GND_A (in), DC_GND_B (in), Coolant_IN_2 (in), Coolant_OUT_2 (out), GND (in)
Unfolder = Unfolder.SchDoc: Phase_B' (in), Phase_A' (in), N (out), P (out), O (out), Phase_C' (in), Coolant_IN_2 (in), Coolant_OUT_2 (out), Coolant_IN_1 (in), Coolant_OUT_1 (out), C_Sens, B_Sens, A_Sens
WAVE Control Box = box.SchDoc (file not in this document): 24V_DC_WAVE (out), DC_GND_WAVE (out), HMI_Chillers (out), CAN_L (in), CAN_H (in)

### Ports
24V_DC_A (in), 24V_DC_B (in), 24V_DC_CC (in), 24V_DC_SMOKE (in), 24V_DC_WAVE (out), CAN_CC (bidir), CAN_WAVE (bidir), Contactor_Control_24VDC (out), Contactor_Control_DC_GND (in), Coolant_IN (in), Coolant_OUT (out), DC_GND_A (in), DC_GND_B (in), DC_GND_CC (in), DC_GND_SMOKE (in), DC_GND_WAVE (out), GND (in), Grid_Comms (in), Grid_Faults (in), HMI_CAN (in), HMI_Chillers (out), Phase_A' (in), Phase_B' (in), Phase_C' (in), Pre-Charge Control_24VDC (out), Pre-Charge_Control_DC_GND (in), QC_1 (out), QC_2 (out), QC_3 (out), QC_4 (out), QC_5 (out), QC_6 (out), QC_7 (out), QC_8 (out), SEC_IN (in), SEC_OUT (out)

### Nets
24V_DC_A: port 24V_DC_A, sheet T-Type System/24V_DC_A
24V_DC_B: port 24V_DC_B, sheet T-Type System/24V_DC_B
24V_DC_CC: port 24V_DC_CC, sheet Smoke Controller/6 (COM)
24V_DC_SMOKE: port 24V_DC_SMOKE, sheet Smoke Controller/9 (24V+)
24V_DC_WAVE: port 24V_DC_WAVE, sheet WAVE Control Box/24V_DC_WAVE
CAN_CC: port CAN_CC, sheet Central Controller/CAN_CC
CAN_WAVE: port CAN_WAVE, sheet WAVE Control Box/CAN_L, sheet WAVE Control Box/CAN_H
Contactor_Control_24VDC: port Contactor_Control_24VDC, sheet Central Controller/Contactor_Control_24VDC
Contactor_Control_DC_GND: port Contactor_Control_DC_GND, sheet Central Controller/Contactor_Control_DC_GND
DC_GND_A: port DC_GND_A, sheet T-Type System/DC_GND_A
DC_GND_B: port DC_GND_B, sheet T-Type System/DC_GND_B
DC_GND_CC: port DC_GND_CC, sheet Central Controller/DC_GND
DC_GND_SMOKE: port DC_GND_SMOKE, sheet Smoke Controller/10 (DC_GND)
DC_GND_WAVE: port DC_GND_WAVE, sheet WAVE Control Box/DC_GND_WAVE
GND: port GND, sheet T-Type System/GND
Grid_Comms: port Grid_Comms, sheet Central Controller/Grid_Comms
Grid_Faults: port Grid_Faults, sheet Central Controller/Grid_Faults
HMI_CAN: port HMI_CAN, sheet Central Controller/HMI_CAN
HMI_Chillers: port HMI_Chillers, sheet WAVE Control Box/HMI_Chillers
N: sheet Fuse Block/N, sheet Unfolder/N
N_1_M{1-8}: sheet Fuse Block/N_1_M{1-8}, sheet T-Type System/N_1_M{1-8}
N_2_M{1-8}: sheet Fuse Block/N_2_M{1-8}, sheet T-Type System/N_2_M{1-8}
O: sheet Fuse Block/O, sheet Unfolder/O
O_1_M{1-8}: sheet Fuse Block/O_1_M{1-8}, sheet T-Type System/O_1_M{1-8}
O_2_M{1-8}: sheet Fuse Block/O_2_M{1-8}, sheet T-Type System/O_2_M{1-8}
P: sheet Fuse Block/P, sheet Unfolder/P
P_1_M{1-8}: sheet Fuse Block/P_1_M{1-8}, sheet T-Type System/P_1_M{1-8}
P_2_M{1-8}: sheet Fuse Block/P_2_M{1-8}, sheet T-Type System/P_2_M{1-8}
Phase_A': port Phase_A', sheet Unfolder/Phase_A'
Phase_B': port Phase_B', sheet Unfolder/Phase_B'
Phase_C': port Phase_C', sheet Unfolder/Phase_C'
Pre-Charge Control_24VDC: port Pre-Charge Control_24VDC, sheet Central Controller/Pre-Charge Control_24VDC
Pre-Charge_Control_DC_GND: port Pre-Charge_Control_DC_GND, sheet Central Controller/Pre-Charge_Control_DC_GND
QC_1: port QC_1, sheet T-Type System/QC_1
QC_2: port QC_2, sheet T-Type System/QC_2
QC_3: port QC_3, sheet T-Type System/QC_3
QC_4: port QC_4, sheet T-Type System/QC_4
QC_5: port QC_5, sheet T-Type System/QC_5
QC_6: port QC_6, sheet T-Type System/QC_6
QC_7: port QC_7, sheet T-Type System/QC_7
QC_8: port QC_8, sheet T-Type System/QC_8
(unnamed): sheet Central Controller/24V_DC, sheet Smoke Controller/16 (N.C.)
(unnamed): sheet Central Controller/M_Fault_OUT, sheet T-Type System/M_Fault_OUT  [a separate net that carries the same name]
(unnamed): sheet Central Controller/M_Fault_IN, sheet T-Type System/M_Fault_IN  [a separate net that carries the same name]
(unnamed): sheet Central Controller/M_Comms_OUT, sheet T-Type System/M_Comms_IN  [a separate net that carries the same name]
(unnamed): sheet Central Controller/C_Sens, sheet Unfolder/C_Sens  [a separate net that carries the same name]
(unnamed): sheet Central Controller/B_Sens, sheet Unfolder/B_Sens  [a separate net that carries the same name]
(unnamed): sheet Central Controller/A_Sens, sheet Unfolder/A_Sens  [a separate net that carries the same name]
(unnamed): sheet Smoke Controller/J1, sheet Smoke Sensor 1/J1  [a separate net that carries the same name]
(unnamed): sheet Smoke Controller/J2, sheet Smoke Sensor 2/J1  [a separate net that carries the same name]

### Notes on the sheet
- Legend
- Port Color Definitions:
- Optical Fiber Connection
- Manifold
- Shielded Ethernet Connection
- Standard Electrical Connection
- Coolant Tubing
- 4 x 313 MCM DLO
- 1 AWG
- 6 AWG
- Quad Cables
- 10 AWG
- CAN Network to send information about power control, states, and statuses.
- 2/0
- To Terminal Block
- Ribbon Cable
- 22 AWG
- x4 Wires
- 14 AWG

## Sheet Fuse_Block.SchDoc: <Document>
size Letter; Engineer: <Engineer>; Organization: UPEL; Address1: USU Power Electronics Lab; Address2: USTAR Building 620, RM 118; Address3: 1600 N 620 E; Address4: North Logan, UT 84341; DocumentNumber: 6; Revision: v1; SheetNumber: 6; SheetTotal: 16
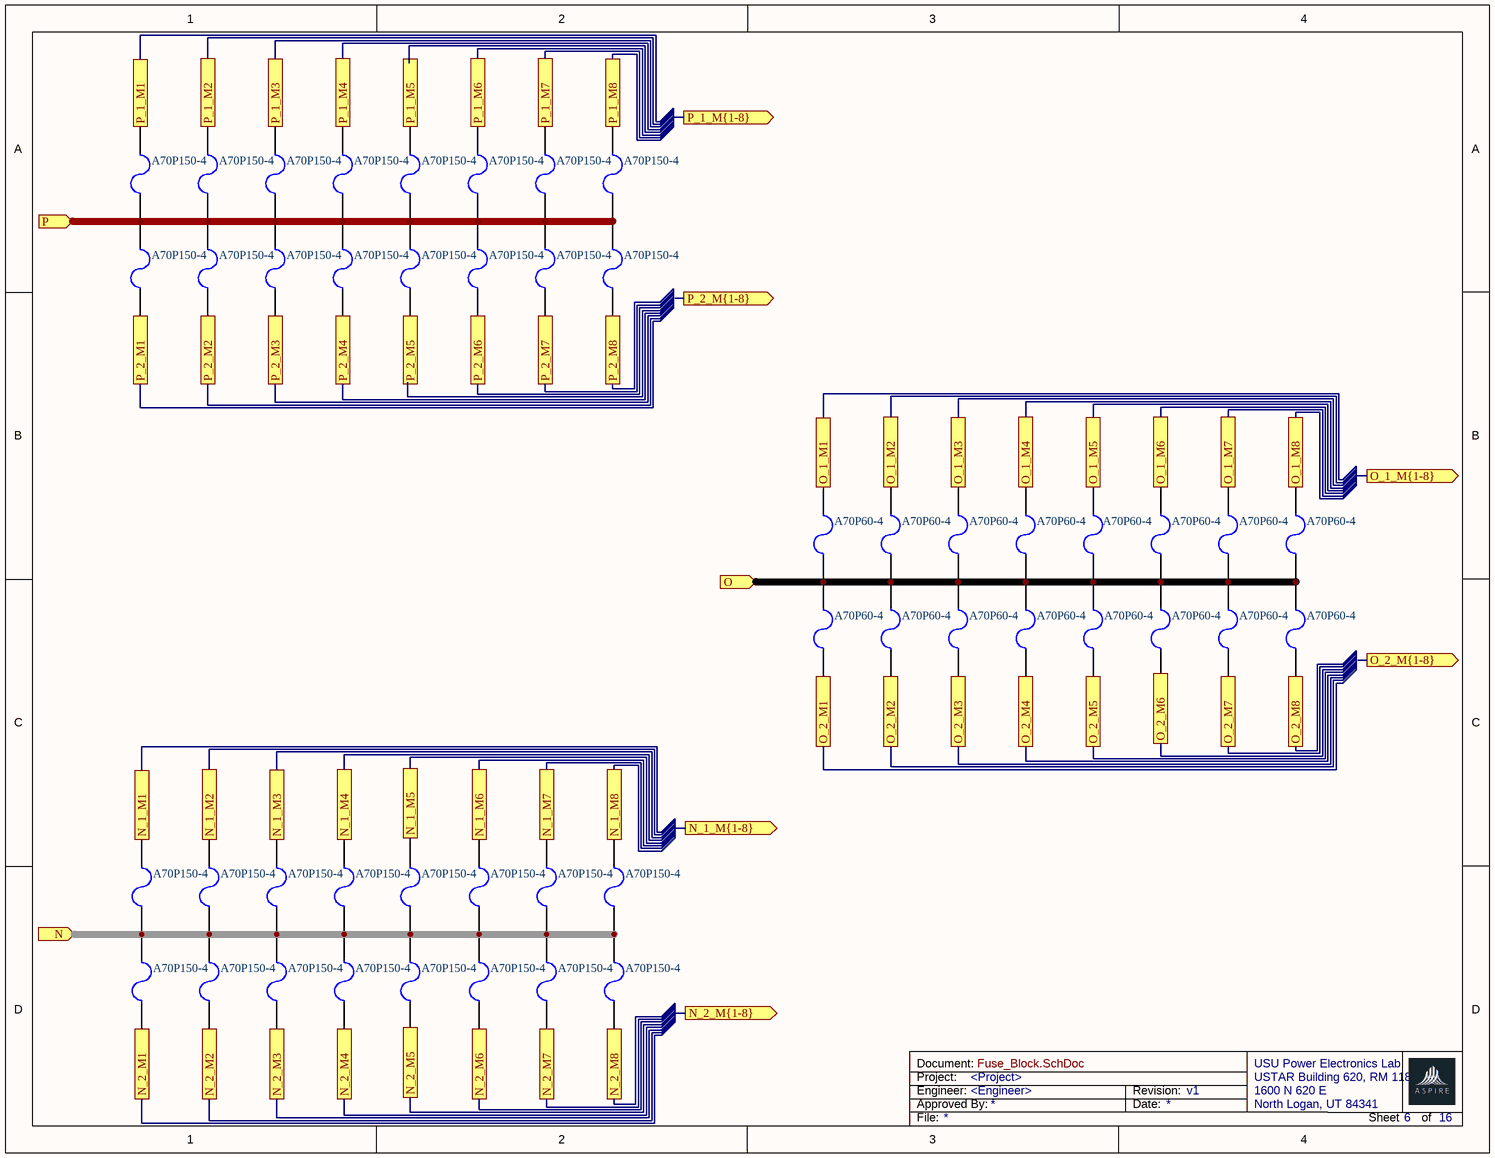
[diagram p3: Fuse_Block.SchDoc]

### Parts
F6  A70P150-4  [1206]
F17  A70P150-4  [1206]
F18  A70P150-4  [1206]
F19  A70P150-4  [1206]
F20  A70P150-4  [1206]
F21  A70P150-4  [1206]
F22  A70P150-4  [1206]
F23  A70P150-4  [1206]
F24  A70P150-4  [1206]
F25  A70P150-4  [1206]
F26  A70P150-4  [1206]
F27  A70P150-4  [1206]
F28  A70P150-4  [1206]
F29  A70P150-4  [1206]
F30  A70P150-4  [1206]
F31  A70P150-4  [1206]
F32  A70P60-4  [1206]
F33  A70P60-4  [1206]
F34  A70P60-4  [1206]
F35  A70P60-4  [1206]
F36  A70P60-4  [1206]
F37  A70P60-4  [1206]
F38  A70P60-4  [1206]
F39  A70P60-4  [1206]
F40  A70P60-4  [1206]
F41  A70P60-4  [1206]
F42  A70P60-4  [1206]
F43  A70P60-4  [1206]
F44  A70P60-4  [1206]
F45  A70P60-4  [1206]
F46  A70P60-4  [1206]
F47  A70P60-4  [1206]
F48  A70P150-4  [1206]
F49  A70P150-4  [1206]
F50  A70P150-4  [1206]
F51  A70P150-4  [1206]
F52  A70P150-4  [1206]
F53  A70P150-4  [1206]
F54  A70P150-4  [1206]
F55  A70P150-4  [1206]
F56  A70P150-4  [1206]
F57  A70P150-4  [1206]
F58  A70P150-4  [1206]
F59  A70P150-4  [1206]
F60  A70P150-4  [1206]
F61  A70P150-4  [1206]
F62  A70P150-4  [1206]
F63  A70P150-4  [1206]

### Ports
N (in), N_1_M1, N_1_M2, N_1_M3, N_1_M4, N_1_M5, N_1_M6, N_1_M7, N_1_M8, N_1_M{1-8} (out), N_2_M1, N_2_M2, N_2_M3, N_2_M4, N_2_M5, N_2_M6, N_2_M7, N_2_M8, N_2_M{1-8} (out), O (in), O_1_M1, O_1_M2, O_1_M3, O_1_M4, O_1_M5, O_1_M6, O_1_M7, O_1_M8, O_1_M{1-8} (out), O_2_M1, O_2_M2, O_2_M3, O_2_M4, O_2_M5, O_2_M6, O_2_M7, O_2_M8, O_2_M{1-8} (out), P (in), P_1_M1, P_1_M2, P_1_M3, P_1_M4, P_1_M5, P_1_M6, P_1_M7, P_1_M8, P_1_M{1-8} (out), P_2_M1, P_2_M2, P_2_M3, P_2_M4, P_2_M5, P_2_M6, P_2_M7, P_2_M8, P_2_M{1-8} (out)

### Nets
N: F48.1 F49.1 F50.1 F51.1 F52.1 F53.1 F54.1 F55.1 F56.2 F57.2 F58.2 F59.2 F60.2 F61.2 F62.2 F63.2 ; port N
N_1_M1: F48.2 ; port N_1_M1
N_1_M2: F49.2 ; port N_1_M2
N_1_M3: F50.2 ; port N_1_M3
N_1_M4: F51.2 ; port N_1_M4
N_1_M5: F52.2 ; port N_1_M5
N_1_M6: F53.2 ; port N_1_M6
N_1_M7: F54.2 ; port N_1_M7
N_1_M8: F55.2 ; port N_1_M8
N_2_M1: F56.1 ; port N_2_M1
N_2_M2: F57.1 ; port N_2_M2
N_2_M3: F58.1 ; port N_2_M3
N_2_M4: F59.1 ; port N_2_M4
N_2_M6: F61.1 ; port N_2_M6
N_2_M7: F62.1 ; port N_2_M7
N_2_M8: F63.1 ; port N_2_M8
O: F32.1 F33.1 F34.1 F35.1 F36.1 F37.1 F38.1 F39.1 F40.2 F41.2 F42.2 F43.2 F44.2 F45.2 F46.2 F47.2 ; port O
O_1_M1: F32.2 ; port O_1_M1
O_1_M2: F33.2 ; port O_1_M2
O_1_M3: F34.2 ; port O_1_M3
O_1_M4: F35.2 ; port O_1_M4
O_1_M5: F36.2 ; port O_1_M5
O_1_M6: F37.2 ; port O_1_M6
O_1_M7: F38.2 ; port O_1_M7
O_1_M8: F39.2 ; port O_1_M8
O_2_M1: F40.1 ; port O_2_M1
O_2_M2: F41.1 ; port O_2_M2
O_2_M3: F42.1 ; port O_2_M3
O_2_M4: F43.1 ; port O_2_M4
O_2_M5: F44.1 ; port O_2_M5
O_2_M7: F46.1 ; port O_2_M7
O_2_M8: F47.1 ; port O_2_M8
P: F6.1 F17.1 F18.1 F19.1 F20.1 F21.1 F22.1 F23.1 F24.2 F25.2 F26.2 F27.2 F28.2 F29.2 F30.2 F31.2 ; port P
P_1_M1: F6.2 ; port P_1_M1
P_1_M2: F17.2 ; port P_1_M2
P_1_M3: F18.2 ; port P_1_M3
P_1_M4: F19.2 ; port P_1_M4
P_1_M5: F20.2 ; port P_1_M5
P_1_M6: F21.2 ; port P_1_M6
P_1_M7: F22.2 ; port P_1_M7
P_1_M8: F23.2 ; port P_1_M8
P_2_M1: F24.1 ; port P_2_M1
P_2_M2: F25.1 ; port P_2_M2
P_2_M3: F26.1 ; port P_2_M3
P_2_M4: F27.1 ; port P_2_M4
P_2_M5: F28.1 ; port P_2_M5
P_2_M6: F29.1 ; port P_2_M6
P_2_M7: F30.1 ; port P_2_M7
P_2_M8: F31.1 ; port P_2_M8

Not connected (* = marked no-connect by the designer): F45 1; F60 1

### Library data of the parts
F6 F17-F63 = CMP-005-000011-1: 2 A 63 V AC 63 V DC Fuse Board Mount (Cartridge Style Excluded) Surface Mount 1206 (3216 Metric)

## Sheet Unfolder.SchDoc: <Document>
size Letter; Engineer: <Engineer>; Organization: UPEL; Address1: USU Power Electronics Lab; Address2: USTAR Building 620, RM 118; Address3: 1600 N 620 E; Address4: North Logan, UT 84341; DocumentNumber: 7; Revision: v1; SheetNumber: 7; SheetTotal: 16
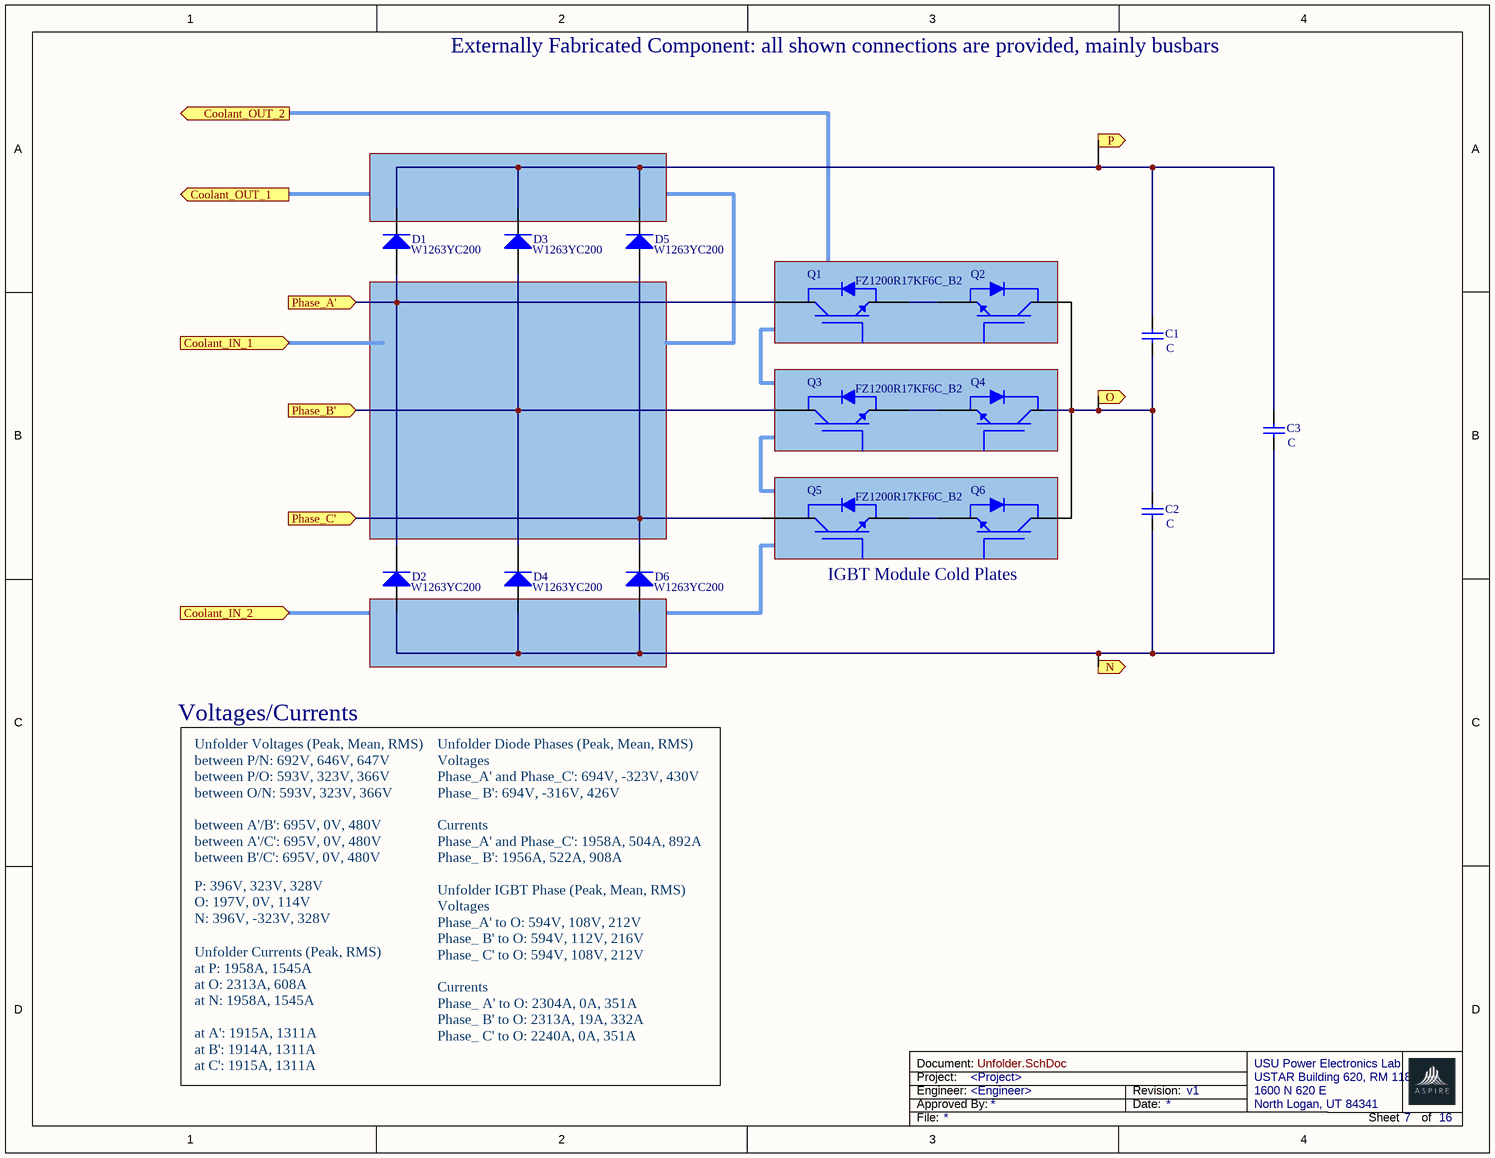
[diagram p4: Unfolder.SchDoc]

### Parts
(Parts that share a designator on the sheet are numbered #1, #2 ... from top to bottom, then left to right.)
C1  value C  [RAD-0.3]  (hidden comment: Cap)
C2  value C  [RAD-0.3]  (hidden comment: Cap)
C3  value C  [RAD-0.3]  (hidden comment: Cap)
D1#1  Diode  [SMC]  (value not drawn)
D2#1  Diode  [SMC]  (value not drawn)
D3#1  Diode  [SMC]  (value not drawn)
D4#1  Diode  [SMC]  (value not drawn)
D5#1  Diode  [SMC]  (value not drawn)
D6#1  Diode  [SMC]  (value not drawn)
Q1  IGBT_Module_1  (value not drawn)
Q2  IGBT_Module_2  (value not drawn)
Q3  IGBT_Module_1  (value not drawn)
Q4  IGBT_Module_2  (value not drawn)
Q5  IGBT_Module_1  (value not drawn)
Q6  IGBT_Module_2  (value not drawn)

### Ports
Coolant_IN_1 (in), Coolant_IN_2 (in), Coolant_OUT_1 (out), Coolant_OUT_2 (out), N (out), O (out), P (out), Phase_A' (in), Phase_B' (in), Phase_C' (in)

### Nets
N: C2.2 C3.2 D2#1.1(A) D4#1.1(A) D6#1.1(A) ; port N
O: C1.2 C2.1 ; port O
P: C1.1 C3.1 D1#1.2(K) D3#1.2(K) D5#1.2(K) ; port P
Phase_A': D1#1.1(A) D2#1.2(K) ; port Phase_A'
Phase_B': D3#1.1(A) D4#1.2(K) ; port Phase_B'
Phase_C': D5#1.1(A) D6#1.2(K) ; port Phase_C'

Not connected (* = marked no-connect by the designer): Q1 1(0) 2(1); Q2 1(2) 2(3); Q3 1(0) 2(1); Q4 1(2) 2(3); Q5 1(0) 2(1); Q6 1(2) 2(3)

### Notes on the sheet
- Externally Fabricated Component: all shown connections are provided, mainly busbars
- (near D1#1) W1263YC200
- (near D3#1) W1263YC200
- (near D5#1) W1263YC200
- (near Q1) Q1
- FZ1200R17KF6C_B2
- (near Q3) Q3
- (near Q5) Q5
- (near D2#1) W1263YC200
- (near D4#1) W1263YC200
- (near D6#1) W1263YC200
- IGBT Module Cold Plates
- Voltages/Currents
- Unfolder Voltages (Peak, Mean, RMS)
  between P/N: 692V, 646V, 647V
  between P/O: 593V, 323V, 366V
  between O/N: 593V, 323V, 366V
  between A'/B': 695V, 0V, 480V
  between A'/C': 695V, 0V, 480V
  between B'/C': 695V, 0V, 480V
- P: 396V, 323V, 328V                       O: 197V, 0V, 114V                         N: 396V, -323V, 328V
- Unfolder Diode Phases (Peak, Mean, RMS)
  Voltages
  Phase_A' and Phase_C': 694V, -323V, 430V
  Phase_ B': 694V, -316V, 426V
  Currents
  Phase_A' and Phase_C': 1958A, 504A, 892A
  Phase_ B': 1956A, 522A, 908A
  Unfolder IGBT Phase (Peak, Mean, RMS)
  Voltages
  Phase_A' to O: 594V, 108V, 212V
  Phase_ B' to O: 594V, 112V, 216V
  Phase_ C' to O: 594V, 108V, 212V
  Currents
  Phase_ A' to O: 2304A, 0A, 351A
  Phase_ B' to O: 2313A, 19A, 332A
  Phase_ C' to O: 2240A, 0A, 351A
- Unfolder Currents (Peak, RMS)
  at P: 1958A, 1545A
  at O: 2313A, 608A
  at N: 1958A, 1545A
  at A': 1915A, 1311A
  at B': 1914A, 1311A
  at C': 1915A, 1311A

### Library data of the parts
C1-C3 = Cap: Capacitor
D1#1 D2#1 D3#1 D4#1 D5#1 D6#1 = Diode: Default Diode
